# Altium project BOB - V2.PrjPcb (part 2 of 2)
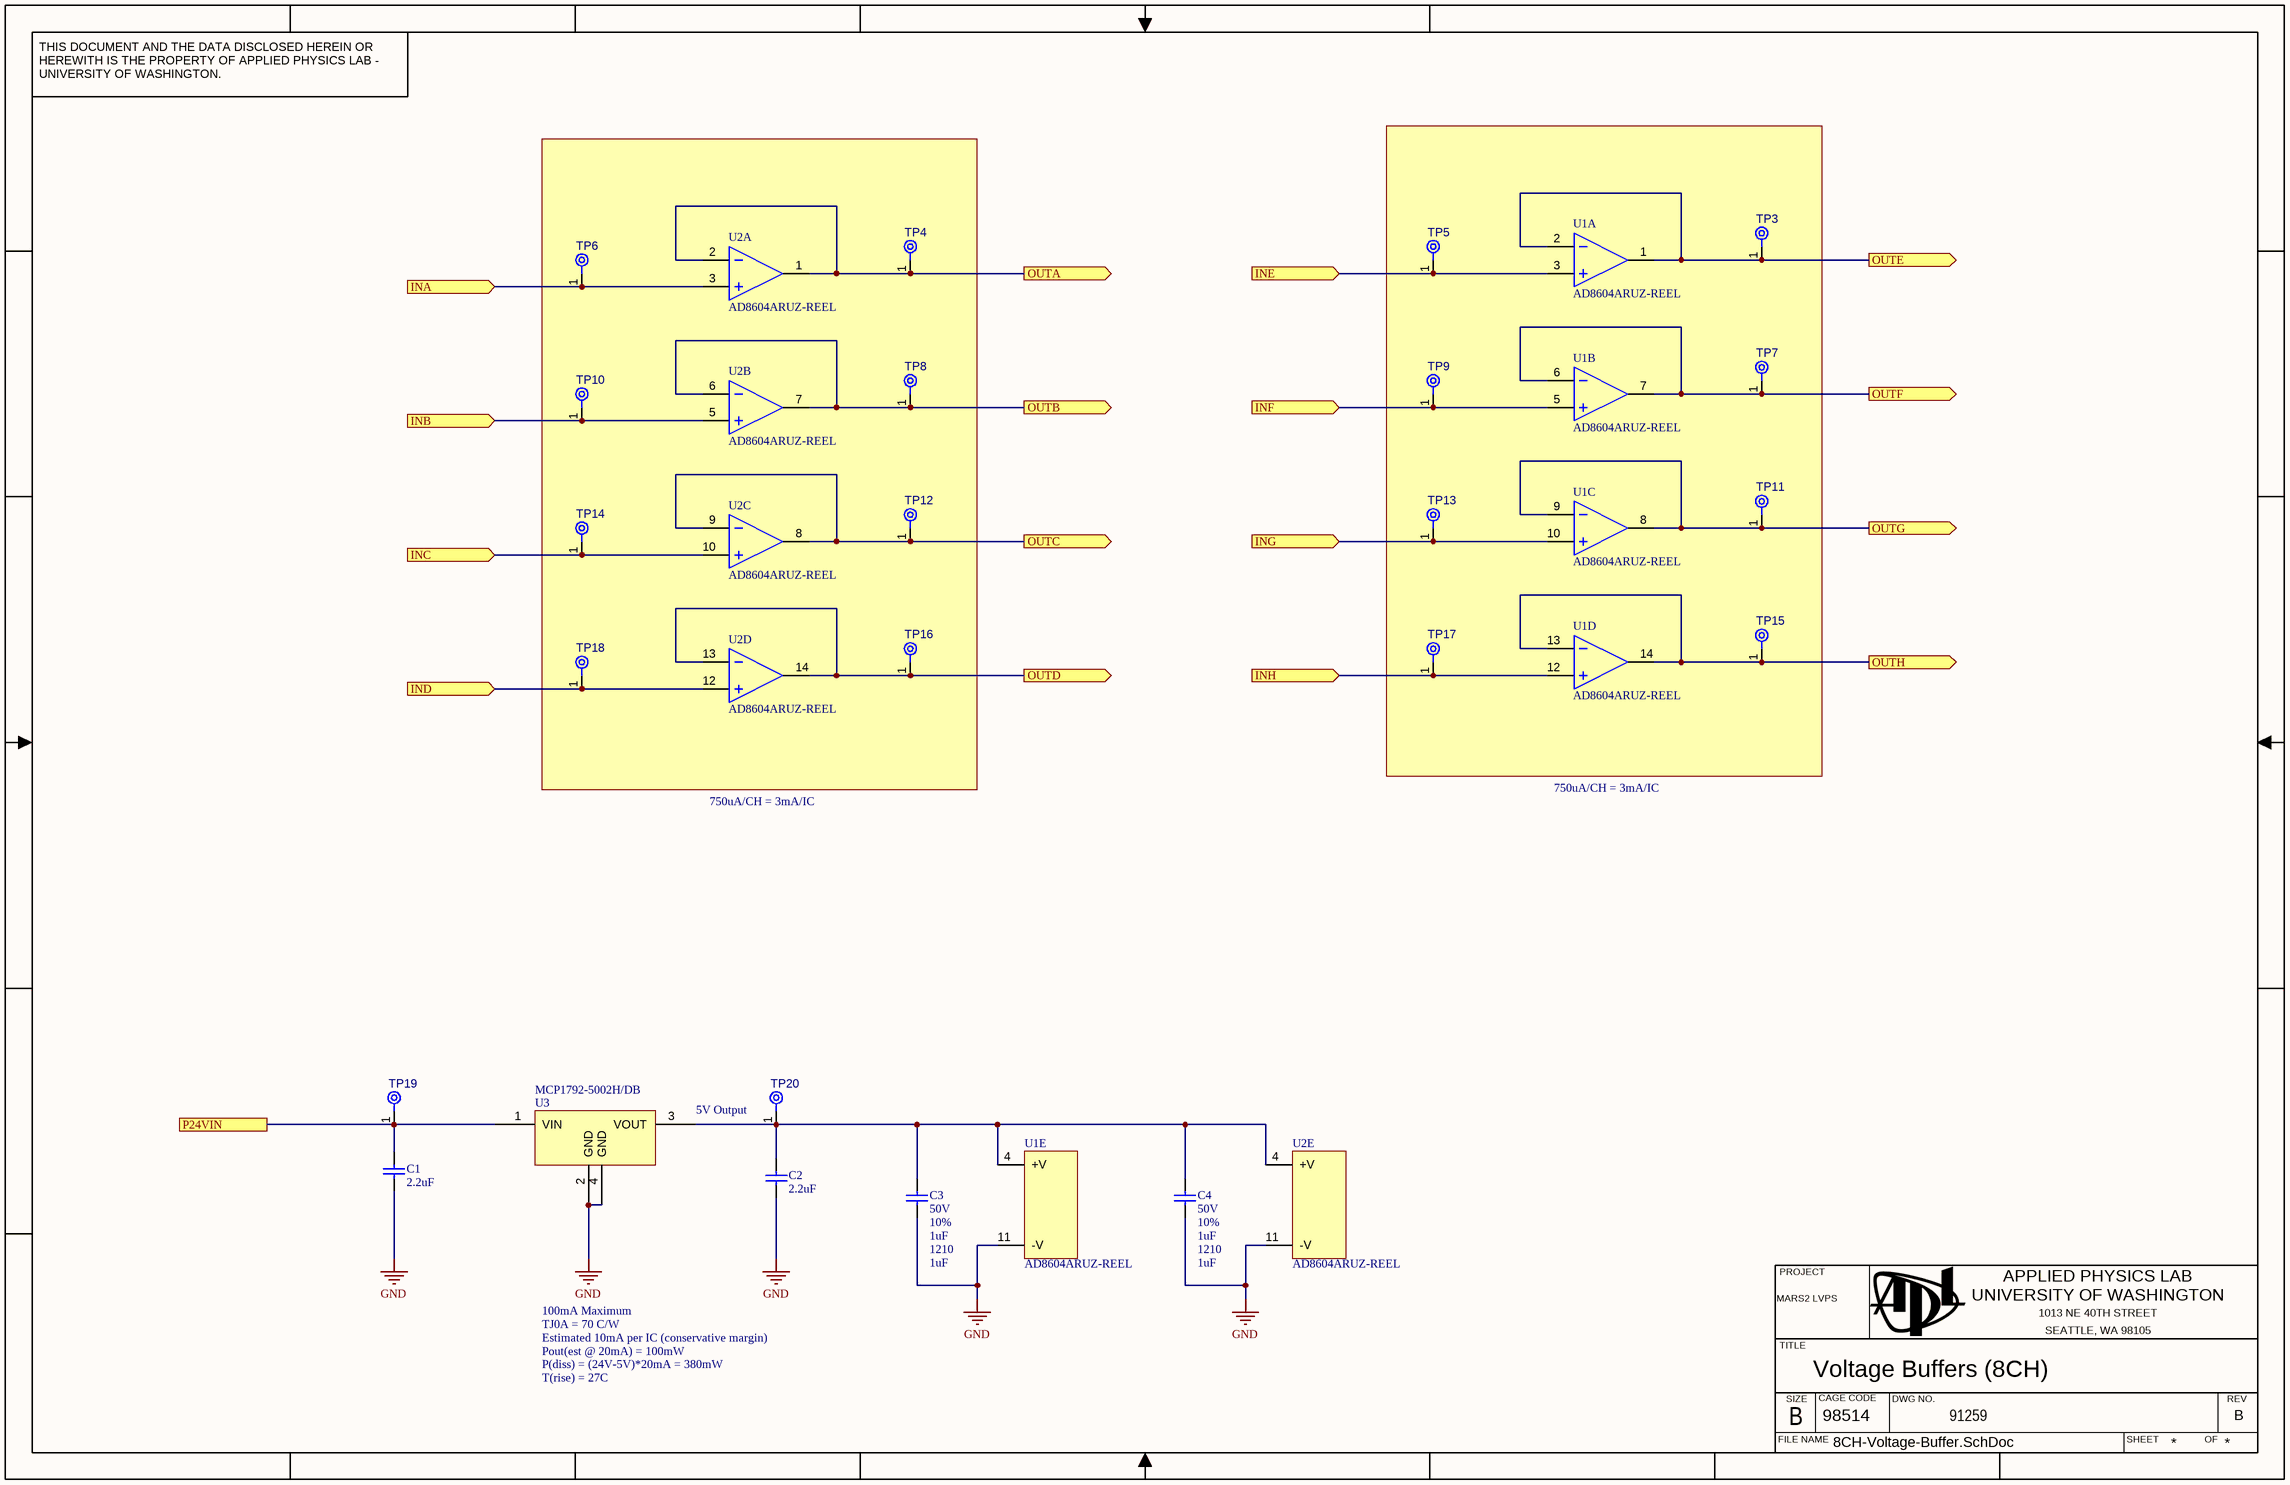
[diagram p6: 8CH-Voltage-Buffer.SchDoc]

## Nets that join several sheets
GND: Coversheet (29 pins), Mezzanine Connector (33 pins), CTI_1 (24 pins), CTI_2 (24 pins), Baycat Breakout (J5.4), Test Points (6 pins), Voltage Buffer - 4CH Bank 1 (8 pins), Voltage Buffer - 4CH Bank 2 (8 pins), Voltage Buffer - 4CH Bank 3 (8 pins), Voltage Buffer - 4CH Bank 4 (8 pins)
SYS_24V: Mezzanine Connector (5 pins), Test Points (TP1.1 TP2.1)
24V_UNSWCH_BUS_CURRENT: Mezzanine Connector (J2.18), Voltage Buffer - 4CH Bank 4 (TP6D.1 U2D.3)
24V_UNSWCH_BUS_CURRENT_BUF: CTI_2 (P1B.15), Voltage Buffer - 4CH Bank 4 (TP4D.1 U2D.1 U2D.2)
BAYCAT_3V3: Mezzanine Connector (J1.18), Baycat Breakout (J5.3)
DIO_SPARE_0: Mezzanine Connector (J1.2), Test Points (J6.1)
DIO_SPARE_1: Mezzanine Connector (J1.4), Test Points (J7.1)
DIO_SPARE_2: Mezzanine Connector (J1.6), Test Points (J8.1)
DIO_SPARE_3: Mezzanine Connector (J1.8), Test Points (J9.1)
DIO_SPARE_4: Mezzanine Connector (J1.10), Test Points (J10.1)
DIO_SPARE_5: Mezzanine Connector (J1.12), Test Points (J13.1)
DIO_SPARE_6: Mezzanine Connector (J1.14), Test Points (J15.1)
DIO_SPARE_7: Mezzanine Connector (J1.16), Test Points (J17.1)
FAULT_MUX_A: Mezzanine Connector (J2.58), CTI_2 (P2B.14)
FAULT_MUX_B: Mezzanine Connector (J2.60), CTI_2 (P2B.13)
FAULT_MUX_C: Mezzanine Connector (J2.62), CTI_2 (P2B.16)
FAULT_SENSE_HPB: Mezzanine Connector (J2.55), CTI_2 (P1B.31)
FAULT_SENSE_IPB1: Mezzanine Connector (J2.51), CTI_2 (P1B.32)
FAULT_SENSE_IPB2: Mezzanine Connector (J2.53), CTI_2 (P1B.33)
GF_AMP_TEMP_F: Mezzanine Connector (J2.59), Voltage Buffer - 4CH Bank 3 (TP10C.1 U2C.5)
GF_AMP_TEMP_F_BUF: CTI_1 (P1A.22), Voltage Buffer - 4CH Bank 3 (TP8C.1 U2C.6 U2C.7)
GF_ANNODE_SEL_EN: Mezzanine Connector (J2.9), CTI_1 (P2A.6)
GF_CHASSIS_SEL_EN: Mezzanine Connector (J2.11), CTI_1 (P2A.5)
GF_SIG: Mezzanine Connector (J2.47), CTI_1 (P1A.11)
GF_SOURCE_SEL_A: Mezzanine Connector (J2.1), CTI_1 (P2A.2)
GF_SOURCE_SEL_B: Mezzanine Connector (J2.3), CTI_1 (P2A.1)
GF_SOURCE_SEL_C: Mezzanine Connector (J2.5), CTI_1 (P2A.4)
GF_SOURCE_SEL_ENn: Mezzanine Connector (J2.7), CTI_1 (P2A.3)
HCB_MEDIA_EN: Mezzanine Connector (J1.30), CTI_2 (P2B.11)
HPB_5V_CURRENT: Mezzanine Connector (J2.34), Voltage Buffer - 4CH Bank 1 (TP9A.1 U1A.5)
HPB_5V_CURRENT_BUF: CTI_2 (P1B.12), Voltage Buffer - 4CH Bank 1 (TP7A.1 U1A.6 U1A.7)
HPB_5V_VOLTAGE: Mezzanine Connector (J2.30), Voltage Buffer - 4CH Bank 1 (TP17A.1 U1A.12)
HPB_5V_VOLTAGE_BUF: CTI_2 (P1B.14), Voltage Buffer - 4CH Bank 1 (TP15A.1 U1A.13 U1A.14)
HPB_24V_CURRENT: Mezzanine Connector (J2.26), Voltage Buffer - 4CH Bank 1 (TP5A.1 U1A.3)
HPB_24V_CURRENT_BUF: CTI_2 (P1B.11), Voltage Buffer - 4CH Bank 1 (TP3A.1 U1A.1 U1A.2)
HPB_24V_VOLTAGE: Mezzanine Connector (J2.22), Voltage Buffer - 4CH Bank 1 (TP13A.1 U1A.10)
HPB_24V_VOLTAGE_BUF: CTI_2 (P1B.13), Voltage Buffer - 4CH Bank 1 (TP11A.1 U1A.8 U1A.9)
HPB_CISCO1_CURRENT: Mezzanine Connector (J2.2), Voltage Buffer - 4CH Bank 1 (TP6A.1 U2A.3)
HPB_CISCO1_CURRENT_BUF: CTI_2 (P1B.5), Voltage Buffer - 4CH Bank 1 (TP4A.1 U2A.1 U2A.2)
HPB_CISCO1_EN: Mezzanine Connector (J1.49), CTI_2 (P2B.10)
HPB_CISCO2_CURRENT: Mezzanine Connector (J2.6), Voltage Buffer - 4CH Bank 1 (TP10A.1 U2A.5)
HPB_CISCO2_CURRENT_BUF: CTI_2 (P1B.6), Voltage Buffer - 4CH Bank 1 (TP8A.1 U2A.6 U2A.7)
HPB_CISCO2_EN: Mezzanine Connector (J1.51), CTI_2 (P2B.9)
HPB_ISO24V_CURRENT: Mezzanine Connector (J2.14), Voltage Buffer - 4CH Bank 1 (TP18A.1 U2A.12)
HPB_ISO24V_CURRENT_BUF: CTI_2 (P1B.8), Voltage Buffer - 4CH Bank 1 (TP16A.1 U2A.13 U2A.14)
HPB_MEDIA_CURRENT: Mezzanine Connector (J2.64), Voltage Buffer - 4CH Bank 3 (TP6C.1 U2C.3)
HPB_MEDIA_CURRENT_BUF: CTI_1 (P1A.5), Voltage Buffer - 4CH Bank 3 (TP4C.1 U2C.1 U2C.2)
HPB_SYNCBOX_CURRENT: Mezzanine Connector (J2.10), Voltage Buffer - 4CH Bank 1 (TP14A.1 U2A.10)
HPB_SYNCBOX_CURRENT_BUF: CTI_2 (P1B.7), Voltage Buffer - 4CH Bank 1 (TP12A.1 U2A.8 U2A.9)
HPB_SYNCBOX_EN: Mezzanine Connector (J1.53), CTI_2 (P2B.12)
HPB_TEMP0: Mezzanine Connector (J1.44), Voltage Buffer - 4CH Bank 3 (TP13C.1 U1C.10)
HPB_TEMP0_F_BUF: CTI_1 (P1A.27), Voltage Buffer - 4CH Bank 3 (TP11C.1 U1C.8 U1C.9)
HPB_TEMP1: Mezzanine Connector (J1.46), Voltage Buffer - 4CH Bank 3 (TP17C.1 U1C.12)
HPB_TEMP1_F_BUF: CTI_1 (P1A.28), Voltage Buffer - 4CH Bank 3 (TP15C.1 U1C.13 U1C.14)
HPB_TEMP2: Mezzanine Connector (J1.48), Voltage Buffer - 4CH Bank 2 (TP6B.1 U2B.3)
HPB_TEMP2_F_BUF: CTI_1 (P1A.31), Voltage Buffer - 4CH Bank 2 (TP4B.1 U2B.1 U2B.2)
HPB_TEMP3: Mezzanine Connector (J1.50), Voltage Buffer - 4CH Bank 2 (TP10B.1 U2B.5)
HPB_TEMP3_F_BUF: CTI_1 (P1A.32), Voltage Buffer - 4CH Bank 2 (TP8B.1 U2B.6 U2B.7)
HPB_TEMP4: Mezzanine Connector (J1.52), Voltage Buffer - 4CH Bank 2 (TP14B.1 U2B.10)
HPB_TEMP4_F_BUF: CTI_1 (P1A.33), Voltage Buffer - 4CH Bank 2 (TP12B.1 U2B.8 U2B.9)
HPB_VICOR1_TEMP: Mezzanine Connector (J1.38), Voltage Buffer - 4CH Bank 3 (TP18C.1 U2C.12)
HPB_VICOR1_TEMP_F_BUF: CTI_1 (P1A.24), Voltage Buffer - 4CH Bank 3 (TP16C.1 U2C.13 U2C.14)
HPB_VICOR2_TEMP: Mezzanine Connector (J1.40), Voltage Buffer - 4CH Bank 3 (TP5C.1 U1C.3)
HPB_VICOR2_TEMP_F_BUF: CTI_1 (P1A.25), Voltage Buffer - 4CH Bank 3 (TP3C.1 U1C.1 U1C.2)
HPB_VICOR3_TEMP: Mezzanine Connector (J1.42), Voltage Buffer - 4CH Bank 3 (TP9C.1 U1C.5)
HPB_VICOR3_TEMP_F_BUF: CTI_1 (P1A.26), Voltage Buffer - 4CH Bank 3 (TP7C.1 U1C.6 U1C.7)
I2C_SCL: Mezzanine Connector (J1.26), Baycat Breakout (J5.1)
I2C_SDA: Mezzanine Connector (J1.22), Baycat Breakout (J5.2)
IGB_TEMP_F: Mezzanine Connector (J2.57), Voltage Buffer - 4CH Bank 3 (TP14C.1 U2C.10)
IGB_TEMP_F_BUF: CTI_1 (P1A.23), Voltage Buffer - 4CH Bank 3 (TP12C.1 U2C.8 U2C.9)
INPUT_FET_LEFT_TEMP_F: Mezzanine Connector (J2.63), Voltage Buffer - 4CH Bank 2 (TP18B.1 U2B.12)
INPUT_FET_LEFT_TEMP_F_BUF: CTI_1 (P1A.34), Voltage Buffer - 4CH Bank 2 (TP16B.1 U2B.13 U2B.14)
INPUT_FET_RIGHT_TEMP_F: Mezzanine Connector (J2.61), Voltage Buffer - 4CH Bank 2 (TP5B.1 U1B.3)
INPUT_FET_RIGHT_TEMP_F_BUF: CTI_1 (P1A.35), Voltage Buffer - 4CH Bank 2 (TP3B.1 U1B.1 U1B.2)
IPB1_BOARD_TEMP: Mezzanine Connector (J1.34), Voltage Buffer - 4CH Bank 2 (TP9B.1 U1B.5)
IPB1_BOARD_TEMP_BUF: CTI_1 (P1A.36), Voltage Buffer - 4CH Bank 2 (TP7B.1 U1B.6 U1B.7)
IPB1_CHA_CURRENT_SET: Mezzanine Connector (J1.1), CTI_1 (P3A.2)
IPB1_CHA_FET_EN: Mezzanine Connector (J1.21), CTI_1 (P2A.7)
IPB1_CHA_I: Mezzanine Connector (J2.15), CTI_1 (P1A.1)
IPB1_CHA_RLY_EN: Mezzanine Connector (J1.17), CTI_1 (P2A.8)
IPB1_CHB_CURRENT_SET: Mezzanine Connector (J1.5), CTI_1 (P3A.4)
IPB1_CHB_FET_EN: Mezzanine Connector (J1.29), CTI_1 (P2A.9)
IPB1_CHB_I: Mezzanine Connector (J2.23), CTI_1 (P1A.2)
IPB1_CHB_RLY_EN: Mezzanine Connector (J1.25), CTI_1 (P2A.10)
IPB1_CHC_CURRENT_SET: Mezzanine Connector (J1.9), CTI_1 (P3A.6)
IPB1_CHC_FET_EN: Mezzanine Connector (J1.37), CTI_1 (P2A.11)
IPB1_CHC_I: Mezzanine Connector (J2.31), CTI_1 (P1A.3)
IPB1_CHC_RLY_EN: Mezzanine Connector (J1.33), CTI_1 (P2A.12)
IPB1_CHD_CURRENT_SET: Mezzanine Connector (J1.13), CTI_1 (P3A.8)
IPB1_CHD_FET_EN: Mezzanine Connector (J1.45), CTI_1 (P2A.13)
IPB1_CHD_I: Mezzanine Connector (J2.39), CTI_1 (P1A.4)
IPB1_CHD_RLY_EN: Mezzanine Connector (J1.41), CTI_1 (P2A.14)
IPB1_RESET: Mezzanine Connector (J2.36), CTI_1 (P2A.16)
IPB2_BOARD_TEMP: Mezzanine Connector (J1.36), Voltage Buffer - 4CH Bank 2 (TP13B.1 U1B.10)
IPB2_BOARD_TEMP_BUF: CTI_1 (P1A.37), Voltage Buffer - 4CH Bank 2 (TP11B.1 U1B.8 U1B.9)
IPB2_CHA_CURRENT_SET: Mezzanine Connector (J1.3), CTI_2 (P3B.2)
IPB2_CHA_FET_EN: Mezzanine Connector (J1.23), CTI_2 (P2B.1)
IPB2_CHA_I: Mezzanine Connector (J2.19), CTI_2 (P1B.1)
IPB2_CHA_RLY_EN: Mezzanine Connector (J1.19), CTI_2 (P2B.2)
IPB2_CHB_CURRENT_SET: Mezzanine Connector (J1.7), CTI_2 (P3B.4)
IPB2_CHB_FET_EN: Mezzanine Connector (J1.31), CTI_2 (P2B.3)
IPB2_CHB_I: Mezzanine Connector (J2.27), CTI_2 (P1B.2)
IPB2_CHB_RLY_EN: Mezzanine Connector (J1.27), CTI_2 (P2B.4)
IPB2_CHC_CURRENT_SET: Mezzanine Connector (J1.11), CTI_2 (P3B.6)
IPB2_CHC_FET_EN: Mezzanine Connector (J1.39), CTI_2 (P2B.5)
IPB2_CHC_I: Mezzanine Connector (J2.35), CTI_2 (P1B.3)
IPB2_CHC_RLY_EN: Mezzanine Connector (J1.35), CTI_2 (P2B.6)
IPB2_CHD_CURRENT_SET: Mezzanine Connector (J1.15), CTI_2 (P3B.8)
IPB2_CHD_FET_EN: Mezzanine Connector (J1.47), CTI_2 (P2B.7)
IPB2_CHD_I: Mezzanine Connector (J2.43), CTI_2 (P1B.4)
IPB2_CHD_RLY_EN: Mezzanine Connector (J1.43), CTI_2 (P2B.8)
IPB2_RESET: Mezzanine Connector (J2.38), CTI_2 (P2B.15)
MVC_L_CURRENT: Mezzanine Connector (J2.46), CTI_2 (P1B.16)
MVC_L_VOLTAGE: Mezzanine Connector (J2.54), Voltage Buffer - 4CH Bank 4 (TP10D.1 U2D.5)
MVC_L_VOLTAGE_BUF: CTI_2 (P1B.18), Voltage Buffer - 4CH Bank 4 (TP8D.1 U2D.6 U2D.7)
MVC_R_CURRENT: Mezzanine Connector (J2.42), CTI_2 (P1B.17)
MVC_R_VOLTAGE: Mezzanine Connector (J2.50), Voltage Buffer - 4CH Bank 4 (TP14D.1 U2D.10)
MVC_R_VOLTAGE_BUF: CTI_2 (P1B.21), Voltage Buffer - 4CH Bank 4 (TP12D.1 U2D.8 U2D.9)
NetJ19_1: CTI_1 (P2A.15), Test Points (J19.1)
NetP1A_6: Coversheet (R2.1), CTI_1 (P1A.6)
NetP1A_7: Coversheet (R3.1), CTI_1 (P1A.7)
NetP1A_8: Coversheet (R4.1), CTI_1 (P1A.8)
NetP1A_12: Coversheet (R5.1), CTI_1 (P1A.12)
NetP1A_13: Coversheet (R6.1), CTI_1 (P1A.13)
NetP1A_14: Coversheet (R7.1), CTI_1 (P1A.14)
NetP1A_15: Coversheet (R8.1), CTI_1 (P1A.15)
NetP1A_16: Coversheet (R9.1), CTI_1 (P1A.16)
NetP1A_17: Coversheet (R10.1), CTI_1 (P1A.17)
NetP1A_18: Coversheet (R11.1), CTI_1 (P1A.18)
NetP1A_21: Coversheet (R12.1), CTI_1 (P1A.21)
NetP1A_38: Coversheet (R24.1), CTI_1 (P1A.38)
NetP1B_22: Coversheet (R13.2), CTI_2 (P1B.22)
NetP1B_23: Coversheet (R14.2), CTI_2 (P1B.23)
NetP1B_24: Coversheet (R15.2), CTI_2 (P1B.24)
NetP1B_25: Coversheet (R16.2), CTI_2 (P1B.25)
NetP1B_26: Coversheet (R17.2), CTI_2 (P1B.26)
NetP1B_27: Coversheet (R18.2), CTI_2 (P1B.27)
NetP1B_28: Coversheet (R19.2), CTI_2 (P1B.28)
NetP1B_34: Coversheet (R20.2), CTI_2 (P1B.34)
NetP1B_35: Coversheet (R21.2), CTI_2 (P1B.35)
NetP1B_36: Coversheet (R22.2), CTI_2 (P1B.36)
NetP1B_37: Coversheet (R23.2), CTI_2 (P1B.37)
NetP1B_38: Coversheet (R25.2), CTI_2 (P1B.38)
NetR1_2: Coversheet (R1.2), Voltage Buffer - 4CH Bank 4 (TP17D.1 U1D.12)
NetR26_2: Coversheet (R26.2), Voltage Buffer - 4CH Bank 4 (TP13D.1 U1D.10)
NetR27_2: Coversheet (R27.2), Voltage Buffer - 4CH Bank 4 (TP9D.1 U1D.5)
NetR28_2: Coversheet (R28.2), Voltage Buffer - 4CH Bank 4 (TP5D.1 U1D.3)
NetR29_2: Coversheet (R29.2), Voltage Buffer - 4CH Bank 4 (TP18D.1 U2D.12)
NetTP3D_1: Coversheet (TP22.1), Voltage Buffer - 4CH Bank 4 (TP3D.1 U1D.1 U1D.2)
NetTP7D_1: Coversheet (TP23.1), Voltage Buffer - 4CH Bank 4 (TP7D.1 U1D.6 U1D.7)
NetTP11D_1: Coversheet (TP24.1), Voltage Buffer - 4CH Bank 4 (TP11D.1 U1D.8 U1D.9)
NetTP15D_1: Coversheet (TP25.1), Voltage Buffer - 4CH Bank 4 (TP15D.1 U1D.13 U1D.14)
NetTP16D_1: Coversheet (TP21.1), Voltage Buffer - 4CH Bank 4 (TP16D.1 U2D.13 U2D.14)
